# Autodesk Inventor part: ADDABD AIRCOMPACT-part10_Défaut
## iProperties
Shininess: 64.0
Length Units: 11269
Angle Units: 11279
Time Units: 11290
Mass Units: 11283
Length Display Precision: 3
Angle Display Precision: 2
Compacted: True
Part Number: ADDABD AIRCOMPACT-part10_Défaut
Document SubType Name: Modeling
Created: 2006-01
Material: Par défaut
Designer: riri
Density: 0.0
Volumn: 0.0
Area: 0.0
PropertySet Name: Model Information
Control State: 0
Master: False
Checked Out: False
Author: riri
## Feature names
1. Base1
